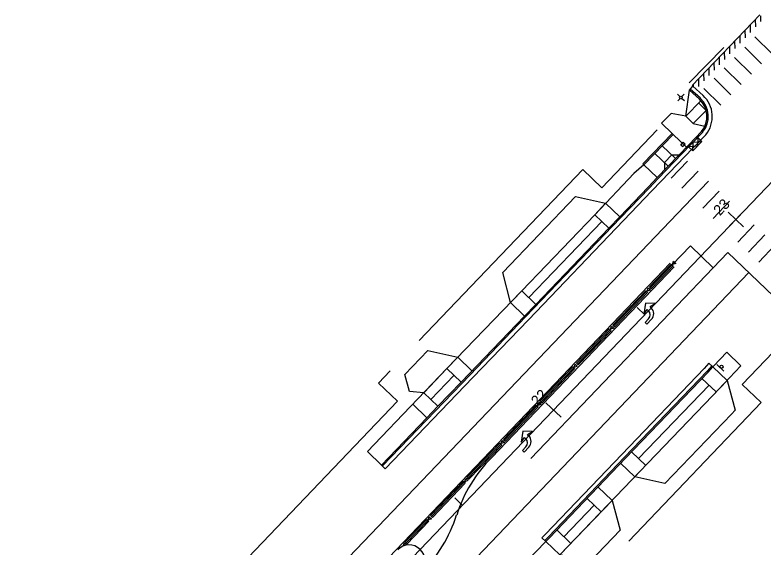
# Model space of a CAD drawing. Extents: x 2377903 to 2496516, y 664638 to 732785.
# Drawn here: x 2378536.6 to 2378820.2, y 730909 to 731110.7 of the extents above; entities that cross this region are included whole.
import ezdxf

# ---------------------------------------------------------------- set-up
doc = ezdxf.new("R2010")
doc.units = 0
for name, color, linetype in [('ALG_CL_BLUE_Horiz', 7, 'Continuous'), ('ALG_CL_BLUE_Horiz-Stationing', 7, 'Continuous'), ('Default', 7, 'Continuous'), ('DES_ROADWAY_Approach', 7, 'Continuous'), ('DES_ROADWAY_Curb-Back', 7, 'Continuous'), ('DES_ROADWAY_Curb-Face', 7, 'Continuous'), ('DES_ROADWAY_Curb-Face-LINE STYLE', 7, 'Continuous'), ('DES_ROADWAY_Edge-of-Pavement', 7, 'Continuous'), ('DES_ROADWAY_Misc-SAW CUT', 7, 'Continuous'), ('DES_ROADWAY_Sidewalk', 7, 'Continuous'), ('ENV_EROSN_Temp-Erosn-Ctrl-Details', 7, 'Continuous'), ('ROW_P_PUA', 7, 'Continuous'), ('TRAF_PAVEMARK_Arrows', 7, 'Continuous'), ('TRAF_PAVEMARK_Stop-Bar', 7, 'Continuous'), ('TRAF_PAVEMARK_White_8-IN', 7, 'Continuous'), ('TRAF_PAVEMARK_White_SKIP 12-38', 7, 'Continuous'), ('TRAF_PAVEMARK_Yellow', 7, 'Continuous'), ('TRAF_PAVEMARK_Yellow-DBL YELLOW', 7, 'Continuous'), ('TRAF_SIGN_Post', 7, 'Continuous'), ('TRAF_SIGNAL_Composite-Junction-Box', 7, 'Continuous'), ('TRAF_WORKZONE_Drum', 7, 'Continuous')]:
    doc.layers.add(name, color=color, linetype=linetype)

# ---------------------------------------------------------------- blocks, each defined once
blk = doc.blocks.new('JCTBOX_5')
at = {"layer": 'Default'}
for p, q in [((-0.0086, 0.0064), (0.0086, 0.0064)), ((-0.0086, 0.0064), (-0.0086, -0.0064)), ((0.0086, 0.0064), (0.0086, -0.0064)), ((-0.0086, -0.0064), (0.0086, -0.0064))]:
    blk.add_line(p, q, dxfattribs=at)
blk.add_text('SIG', height=0.00635, dxfattribs=at).set_placement((-0.0063, -0.0031))
blk = doc.blocks.new('STSIGN_4')
at = {"layer": 'Default'}
for p, q in [((-0.0223, 0), (-0.0064, 0)), ((0, 0.0223), (0, 0.0064)), ((0.0064, 0), (0.0223, 0)), ((0, -0.0064), (0, -0.0223))]:
    blk.add_line(p, q, dxfattribs=at)
blk.add_circle((0, 0), 0.00635, dxfattribs=at)

msp = doc.modelspace()

# ---------------------------------------------------------------- linework, layer by layer
at = {"layer": 'ALG_CL_BLUE_Horiz'}
msp.add_line((2378375.43, 730579.33), (2378840.27, 731064.93), dxfattribs=at)
at = {"layer": 'ALG_CL_BLUE_Horiz-Stationing'}
for p, q in [((2378807.02, 731035.98), (2378812.8, 731030.45)), ((2378772.45, 730999.86), (2378775.34, 730997.09)), ((2378737.87, 730963.74), (2378743.65, 730958.21)), ((2378703.3, 730927.62), (2378706.19, 730924.86))]:
    msp.add_line(p, q, dxfattribs=at)
at = {"layer": 'Default'}
for p, q in [((2378731.41, 731003.58), (2378759.05, 731032.44)), ((2378694.28, 730964.95), (2378703.03, 730974.07)), ((2378773.06, 730942.56), (2378799.75, 730970.38)), ((2378744.68, 730912.94), (2378756.14, 730924.91))]:
    msp.add_line(p, q, dxfattribs=at)
at = {"layer": 'DES_ROADWAY_Approach'}
for points in [[(2378760.52, 731039.33), (2378756.38, 731034.99), (2378728.73, 731006.15), (2378724.48, 731001.72), (2378721.51, 731013.07), (2378749.16, 731041.91)], [(2378700.36, 730976.64), (2378691.61, 730967.51), (2378686.14, 730968.03), (2378684.4, 730974.44), (2378693.15, 730983.56), (2378704.51, 730980.96)], [(2378806.56, 730972.16), (2378809.65, 730960.89), (2378808.24, 730959.4), (2378782.96, 730933.07), (2378771.59, 730935.66), (2378773.56, 730937.72), (2378801, 730966.3)], [(2378762.97, 730926.67), (2378766.04, 730915.42), (2378754.57, 730903.46), (2378743.2, 730906.04), (2378746.11, 730909.08)]]:
    msp.add_lwpolyline(points, close=True, dxfattribs=at)
at = {"layer": 'DES_ROADWAY_Curb-Back'}
for p, q in [((2378792.28, 731082.25), (2378796.11, 731078.74)), ((2378777.48, 731007.28), (2378785.77, 731015.95)), ((2378763.65, 730992.83), (2378776.09, 731005.84)), ((2378729.83, 730996.57), (2378708.78, 730974.71)), ((2378749.82, 730978.39), (2378762.26, 730991.39)), ((2378735.99, 730963.94), (2378748.43, 730976.94)), ((2378722.16, 730949.49), (2378734.6, 730962.49)), ((2378708.33, 730935.04), (2378720.77, 730948.05)), ((2378694.5, 730920.6), (2378706.94, 730933.6)), ((2378684.81, 730910.48), (2378693.11, 730919.15))]:
    msp.add_line(p, q, dxfattribs=at)
for points in [[(2378796.95, 731066.54), (2378792.22, 731061.65), (2378780.11, 731049.06), (2378776.65, 731045.45)], [(2378729.83, 730996.57), (2378734.08, 731001.02), (2378761.71, 731029.88), (2378765.86, 731034.22), (2378776.65, 731045.45)], [(2378737.85, 730911.18), (2378739.19, 730912.58), (2378768.06, 730942.7), (2378799.37, 730975.36), (2378801.16, 730977.33)], [(2378675.54, 730940.1), (2378692.79, 730958.06), (2378696.94, 730962.38), (2378705.7, 730971.5), (2378708.78, 730974.71)]]:
    msp.add_lwpolyline(points, dxfattribs=at)
msp.add_arc((2378790.06, 731072.2), 8.91, 320.5747, 47.2792, dxfattribs=at)
at = {"layer": 'DES_ROADWAY_Curb-Face'}
for p, q in [((2378777.11, 731007.63), (2378785.41, 731016.3)), ((2378777.84, 731006.94), (2378786.13, 731015.6)), ((2378785.41, 731016.3), (2378786.13, 731015.6)), ((2378777.11, 731007.63), (2378777.84, 731006.94)), ((2378763.28, 730993.18), (2378775.73, 731006.18)), ((2378764.01, 730992.49), (2378776.45, 731005.49)), ((2378775.73, 731006.18), (2378776.45, 731005.49)), ((2378763.28, 730993.18), (2378764.01, 730992.49)), ((2378749.45, 730978.73), (2378761.9, 730991.73)), ((2378750.18, 730978.04), (2378762.62, 730991.04)), ((2378761.9, 730991.73), (2378762.62, 730991.04)), ((2378749.45, 730978.73), (2378750.18, 730978.04)), ((2378735.62, 730964.28), (2378748.07, 730977.29)), ((2378736.35, 730963.59), (2378748.79, 730976.6)), ((2378748.07, 730977.29), (2378748.79, 730976.6)), ((2378735.62, 730964.28), (2378736.35, 730963.59)), ((2378721.79, 730949.84), (2378734.24, 730962.84)), ((2378722.52, 730949.15), (2378734.96, 730962.15)), ((2378734.24, 730962.84), (2378734.96, 730962.15)), ((2378721.79, 730949.84), (2378722.52, 730949.15)), ((2378707.96, 730935.39), (2378720.41, 730948.39)), ((2378708.69, 730934.7), (2378721.13, 730947.7)), ((2378720.41, 730948.39), (2378721.13, 730947.7)), ((2378694.13, 730920.94), (2378706.58, 730933.94)), ((2378694.86, 730920.25), (2378707.3, 730933.25)), ((2378706.58, 730933.94), (2378707.3, 730933.25)), ((2378707.96, 730935.39), (2378708.69, 730934.7)), ((2378684.45, 730910.83), (2378692.75, 730919.5)), ((2378685.18, 730910.14), (2378693.47, 730918.81)), ((2378692.75, 730919.5), (2378693.47, 730918.81)), ((2378694.13, 730920.94), (2378694.86, 730920.25)), ((2378685.18, 730910.14), (2378684.45, 730910.83))]:
    msp.add_line(p, q, dxfattribs=at)
at = {"layer": 'DES_ROADWAY_Curb-Face-LINE STYLE'}
for p, q in [((2378709.14, 730974.36), (2378730.19, 730996.23)), ((2378675.9, 730939.76), (2378709.14, 730974.36))]:
    msp.add_line(p, q, dxfattribs=at)
for points in [[(2378796.45, 731079.11), (2378796.45, 731079.11), (2378792.62, 731082.61)], [(2378777.01, 731045.11), (2378780.47, 731048.72), (2378792.58, 731061.31), (2378797.32, 731066.2), (2378797.33, 731066.22)], [(2378730.19, 730996.23), (2378766.22, 731033.87), (2378777.01, 731045.11)], [(2378800.79, 730977.67), (2378799.01, 730975.7), (2378767.7, 730943.05), (2378738.83, 730912.92), (2378737.49, 730911.52)]]:
    msp.add_lwpolyline(points, dxfattribs=at)
msp.add_arc((2378790.06, 731072.2), 9.41, 320.5747, 47.2792, dxfattribs=at)
at = {"layer": 'DES_ROADWAY_Edge-of-Pavement'}
for p, q in [((2378793.39, 731083.92), (2378819.03, 731110.71)), ((2378792.28, 731082.25), (2378793.63, 731083.72)), ((2378731.27, 730995.19), (2378710.22, 730973.32)), ((2378799.68, 730978.68), (2378801.16, 730977.33)), ((2378676.99, 730938.72), (2378710.22, 730973.32)), ((2378675.54, 730940.1), (2378676.99, 730938.72)), ((2378736.4, 730912.56), (2378737.85, 730911.18))]:
    msp.add_line(p, q, dxfattribs=at)
for points in [[(2378793.63, 731083.72), (2378797.46, 731080.22), (2378797.47, 731080.21)], [(2378798.49, 731065.27), (2378798.44, 731065.2), (2378793.66, 731060.27), (2378781.55, 731047.68), (2378778.09, 731044.07)], [(2378778.09, 731044.07), (2378767.3, 731032.83), (2378731.27, 730995.19)], [(2378799.68, 730978.68), (2378797.91, 730976.72), (2378766.62, 730944.09), (2378737.75, 730913.96), (2378736.4, 730912.56)]]:
    msp.add_lwpolyline(points, dxfattribs=at)
for centre, radius, start, end in [((2378790.06, 731072.2), 10.91, 320.5747, 47.2792), ((2378686.05, 730903.82), 6, 316.2512, 136.2512)]:
    msp.add_arc(centre, radius, start, end, dxfattribs=at)
at = {"layer": 'DES_ROADWAY_Misc-SAW CUT'}
for p, q in [((2378817.43, 731106.15), (2378817.37, 731108.98)), ((2378819.39, 731108.19), (2378819.34, 731110.39)), ((2378815.48, 731104.1), (2378815.42, 731106.93)), ((2378811.56, 731100.01), (2378811.5, 731102.84)), ((2378813.52, 731102.06), (2378813.46, 731104.89)), ((2378809.6, 731097.97), (2378809.54, 731100.8)), ((2378807.65, 731095.92), (2378807.59, 731098.75)), ((2378803.73, 731091.83), (2378803.67, 731094.66)), ((2378805.69, 731093.88), (2378805.63, 731096.71)), ((2378801.77, 731089.79), (2378801.72, 731092.62)), ((2378799.82, 731087.74), (2378799.76, 731090.57)), ((2378795.9, 731083.65), (2378795.84, 731086.48)), ((2378797.86, 731085.7), (2378797.8, 731088.53)), ((2378793.91, 731083.47), (2378793.89, 731084.44))]:
    msp.add_line(p, q, dxfattribs=at)
at = {"layer": 'DES_ROADWAY_Sidewalk'}
for p, q in [((2378790.91, 731072.32), (2378792.28, 731082.25)), ((2378796.68, 731078.17), (2378790.91, 731072.32)), ((2378798.68, 731074.49), (2378793.76, 731069.51)), ((2378798.68, 731074.49), (2378795.83, 731077.3)), ((2378785.36, 731073.34), (2378781.78, 731069.65)), ((2378790.91, 731072.32), (2378785.36, 731073.34)), ((2378793.76, 731069.51), (2378790.91, 731072.32)), ((2378781.78, 731069.65), (2378785.78, 731065.78)), ((2378793.76, 731069.51), (2378798.18, 731068.51)), ((2378774.69, 731054.25), (2378785.78, 731065.78)), ((2378775.05, 731053.9), (2378786.14, 731065.43)), ((2378786.14, 731065.43), (2378785.78, 731065.78)), ((2378791.2, 731060.59), (2378786.14, 731065.43)), ((2378787.04, 731056.27), (2378781.98, 731061.11)), ((2378784.27, 731053.38), (2378779.21, 731058.22)), ((2378782.82, 731054.77), (2378785.59, 731057.65)), ((2378785.59, 731057.65), (2378788.43, 731057.71)), ((2378782.82, 731054.77), (2378782.88, 731051.94)), ((2378775.05, 731053.9), (2378771.27, 731050.6)), ((2378775.05, 731053.9), (2378774.69, 731054.25)), ((2378780.11, 731049.06), (2378775.05, 731053.9)), ((2378756.38, 731034.99), (2378771.27, 731050.6)), ((2378760.52, 731039.33), (2378765.86, 731034.22)), ((2378728.73, 731006.15), (2378756.38, 731034.99)), ((2378756.38, 731034.99), (2378761.71, 731029.88)), ((2378700.36, 730976.64), (2378728.73, 731006.15)), ((2378728.73, 731006.15), (2378734.08, 731001.02)), ((2378729.83, 730996.57), (2378724.48, 731001.72)), ((2378704.51, 730980.96), (2378709.86, 730975.83)), ((2378806.51, 730982.9), (2378801.45, 730977.65)), ((2378811.85, 730977.75), (2378806.51, 730982.9)), ((2378672.8, 730947.88), (2378700.36, 730976.64)), ((2378700.36, 730976.64), (2378705.7, 730971.5)), ((2378801, 730966.3), (2378811.85, 730977.75)), ((2378801.16, 730977.33), (2378801.45, 730977.65)), ((2378806.56, 730972.16), (2378801.16, 730977.33)), ((2378802.43, 730967.81), (2378797.06, 730972.95)), ((2378691.61, 730967.51), (2378696.94, 730962.38)), ((2378773.56, 730937.72), (2378801, 730966.3)), ((2378687.46, 730963.18), (2378692.79, 730958.06)), ((2378670.23, 730945.21), (2378672.8, 730947.88)), ((2378675.54, 730940.1), (2378670.23, 730945.21)), ((2378775.74, 730939.99), (2378770.38, 730945.13)), ((2378771.59, 730935.66), (2378766.23, 730940.79)), ((2378746.11, 730909.08), (2378773.56, 730937.72)), ((2378762.97, 730926.67), (2378757.62, 730931.81)), ((2378758.82, 730922.34), (2378753.47, 730927.47)), ((2378747.35, 730910.38), (2378742, 730915.51)), ((2378737.85, 730911.18), (2378730.44, 730903.42)), ((2378743.2, 730906.04), (2378737.85, 730911.18)), ((2378735.79, 730898.31), (2378746.11, 730909.08))]:
    msp.add_line(p, q, dxfattribs=at)
at = {"layer": 'ENV_EROSN_Temp-Erosn-Ctrl-Details'}
msp.add_lwpolyline([(2378797.05, 731062.76), (2378793.57, 731059.17), (2378791.99, 731060.7), (2378795.47, 731064.29)], close=True, dxfattribs=at)
for points in [[(2378795.47, 731064.29), (2378795.31, 731060.97), (2378791.99, 731060.7)], [(2378793.57, 731059.17), (2378793.73, 731062.5), (2378797.05, 731062.76)]]:
    msp.add_lwpolyline(points, dxfattribs=at)
at = {"layer": 'ROW_P_PUA'}
for p, q in [((2378759.08, 731045.19), (2378780.11, 731067.15)), ((2378689.88, 730987.36), (2378751.86, 731052.1)), ((2378751.86, 731052.1), (2378759.08, 731045.19)), ((2378812.34, 730970.67), (2378845.13, 731004.93)), ((2378674.41, 730971.2), (2378678.81, 730975.8)), ((2378674.41, 730971.2), (2378681.63, 730964.28)), ((2378819.56, 730963.76), (2378812.34, 730970.67)), ((2378590.01, 730868.57), (2378681.63, 730964.28)), ((2378769.33, 730911.29), (2378819.56, 730963.76))]:
    msp.add_line(p, q, dxfattribs=at)
at = {"layer": 'TRAF_PAVEMARK_Arrows'}
for p, q in [((2378775.6, 731001.44), (2378775.03, 730997.25)), ((2378779.34, 731001.3), (2378775.6, 731001.44)), ((2378777.39, 731000.16), (2378779.34, 731001.3)), ((2378775.03, 730997.25), (2378776.31, 730999.04)), ((2378776.31, 730999.04), (2378776.76, 730998.61)), ((2378777.84, 730999.73), (2378777.39, 731000.16)), ((2378776.83, 730995.54), (2378775.54, 730994.19)), ((2378776.21, 730993.55), (2378777.93, 730995.34)), ((2378775.54, 730994.19), (2378776.21, 730993.55)), ((2378729.1, 730952.93), (2378728.53, 730948.74)), ((2378732.83, 730952.78), (2378729.1, 730952.93)), ((2378730.88, 730951.65), (2378732.83, 730952.78)), ((2378728.53, 730948.74), (2378729.81, 730950.53)), ((2378729.81, 730950.53), (2378730.25, 730950.1)), ((2378731.33, 730951.22), (2378730.88, 730951.65)), ((2378730.32, 730947.02), (2378729.03, 730945.68)), ((2378729.7, 730945.04), (2378731.42, 730946.83)), ((2378729.03, 730945.68), (2378729.7, 730945.04))]:
    msp.add_line(p, q, dxfattribs=at)
for centre, radius in [((2378775.26, 730997.04), 2.17), ((2378775.69, 730997.49), 3.1), ((2378728.75, 730948.53), 2.17), ((2378729.18, 730948.98), 3.1)]:
    msp.add_arc(centre, radius, 316.2016, 46.2016, dxfattribs=at)
at = {"layer": 'TRAF_PAVEMARK_Stop-Bar'}
for p, q in [((2378823.53, 731096.08), (2378817.12, 731102.41)), ((2378805.37, 731098.34), (2378792.2, 731085.01)), ((2378819.66, 731092.17), (2378813.26, 731098.5)), ((2378815.8, 731088.26), (2378809.39, 731094.59)), ((2378811.93, 731084.35), (2378805.53, 731090.67)), ((2378808.06, 731080.44), (2378801.66, 731086.76)), ((2378804.2, 731076.52), (2378797.8, 731082.85)), ((2378785.41, 731048.83), (2378791.63, 731055.33)), ((2378789.38, 731045.03), (2378795.61, 731051.53)), ((2378793.36, 731041.22), (2378799.58, 731047.72)), ((2378797.33, 731037.42), (2378803.55, 731043.92)), ((2378801.3, 731033.62), (2378807.52, 731040.12)), ((2378805.99, 731029.13), (2378812.22, 731035.63)), ((2378810.69, 731024.63), (2378816.92, 731031.13)), ((2378814.67, 731020.82), (2378820.89, 731027.33)), ((2378818.64, 731017.02), (2378824.86, 731023.52)), ((2378792.69, 731023.17), (2378801.36, 731014.88)), ((2378806.89, 731020.65), (2378824.17, 731004.11))]:
    msp.add_line(p, q, dxfattribs=at)
at = {"layer": 'TRAF_PAVEMARK_White_8-IN'}
msp.add_line((2378732.21, 730942.64), (2378806.89, 731020.65), dxfattribs=at)
at = {"layer": 'TRAF_PAVEMARK_White_SKIP 12-38'}
for p, q in [((2378398.38, 730628.61), (2378793.36, 731041.22)), ((2378421.23, 730601.86), (2378814.84, 731013.05))]:
    msp.add_line(p, q, dxfattribs=at)
at = {"layer": 'TRAF_PAVEMARK_Yellow'}
for p, q in [((2378523.4, 730743.31), (2378785.05, 731016.64)), ((2378717.35, 730943.02), (2378786.5, 731015.26))]:
    msp.add_line(p, q, dxfattribs=at)
for centre, start, end in [((2378756.18, 730904.41), 135.1621, 162.1744), ((2378651.91, 730937.94), 315.1621, 342.1744)]:
    msp.add_arc(centre, 54.76, start, end, dxfattribs=at)
at = {"layer": 'TRAF_PAVEMARK_Yellow-DBL YELLOW'}
msp.add_line((2378785.77, 731015.95), (2378792.69, 731023.17), dxfattribs=at)
at = {"layer": 'TRAF_SIGN_Post'}
msp.add_line((2378805.35, 730975.68), (2378802.75, 730978.18), dxfattribs=at)
msp.add_circle((2378804.47, 730977.36), 0.6, dxfattribs=at)
at = {"layer": 'TRAF_WORKZONE_Drum'}
for points in [[(2378785.95, 731016.13), (2378786.32, 731017.33), (2378787.13, 731016.55)], [(2378776.27, 731006.02), (2378776.64, 731007.22), (2378777.45, 731006.44)], [(2378762.44, 730991.57), (2378762.81, 730992.77), (2378763.62, 730991.99)], [(2378748.61, 730977.12), (2378748.98, 730978.32), (2378749.79, 730977.55)], [(2378734.78, 730962.67), (2378735.15, 730963.88), (2378735.96, 730963.1)], [(2378720.95, 730948.23), (2378721.32, 730949.43), (2378722.13, 730948.65)], [(2378707.12, 730933.78), (2378707.49, 730934.98), (2378708.3, 730934.2)], [(2378693.29, 730919.33), (2378693.66, 730920.53), (2378694.47, 730919.76)], [(2378683.95, 730909.58), (2378684.32, 730910.78), (2378685.13, 730910)]]:
    msp.add_lwpolyline(points, close=True, dxfattribs=at)

# ---------------------------------------------------------------- block references
at = {"layer": 'TRAF_SIGN_Post', "xscale": 78.74, "yscale": 78.74000000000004, "rotation": -42.45348059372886}
msp.add_blockref('STSIGN_4', (2378789.1, 731079.44), dxfattribs=at)
at = {"layer": 'TRAF_SIGNAL_Composite-Junction-Box', "xscale": 78.74000000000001, "yscale": 78.74000000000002, "rotation": 47.04889002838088}
msp.add_blockref('JCTBOX_5', (2378789.86, 731061.64), dxfattribs=at)

# ---------------------------------------------------------------- texts
at = {"layer": 'ALG_CL_BLUE_Horiz-Stationing'}
for s, p in [('23', (2378803.85, 731034.4)), ('22', (2378734.7, 730962.16))]:
    msp.add_text(s, height=4, rotation=46.2512, dxfattribs=at).set_placement(p)

doc.saveas('drawing.dxf')
